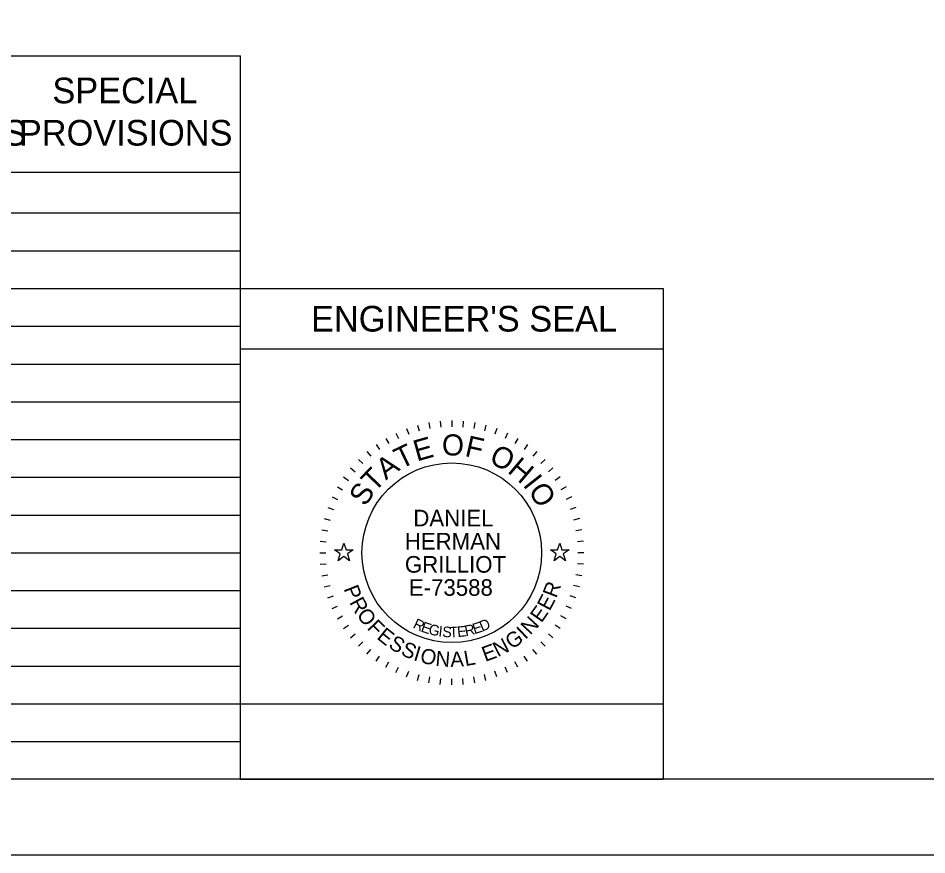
# Model space of a CAD drawing. Extents: x 0 to 34, y 0 to 22.
# Drawn here: x 22.13 to 28.15, y 0 to 5.54 of the extents above; entities that cross this region are included whole.
import ezdxf

# ---------------------------------------------------------------- set-up
doc = ezdxf.new("R2010")
doc.units = 0
for name, color, linetype in [('SH_Border', 7, 'Continuous'), ('SH_Cut_Line', 7, 'Continuous'), ('SH_Data', 7, 'Continuous'), ('SH_Seal', 7, 'Continuous'), ('SH_Text', 7, 'Continuous')]:
    doc.layers.add(name, color=color, linetype=linetype)

msp = doc.modelspace()

# ---------------------------------------------------------------- linework, layer by layer
at = {"layer": 'SH_Border'}
msp.add_lwpolyline([(1.5, 21.5), (33.5, 21.5), (33.5, 0.5), (1.5, 0.5)], close=True, dxfattribs=at)
at = {"layer": 'SH_Cut_Line'}
msp.add_lwpolyline([(0, 0), (34, 0), (34, 22), (0, 22)], close=True, dxfattribs=at)
at = {"layer": 'SH_Data'}
for p, q in [((10.15, 5.2917), (23.6, 5.2917)), ((23.6, 0.5), (23.6, 5.2917)), ((10.15, 4.5209), (23.6, 4.5209)), ((10.15, 4.25), (23.6, 4.25)), ((10.15, 4), (23.6, 4)), ((10.15, 3.75), (23.6, 3.75)), ((23.6, 0.5), (23.6, 3.75)), ((23.6, 3.75), (26.4, 3.75)), ((26.4, 3.75), (26.4, 0.5)), ((10.15, 3.5), (23.6, 3.5)), ((23.6, 3.35), (26.4, 3.35)), ((10.15, 3.25), (23.6, 3.25)), ((10.15, 3), (23.6, 3)), ((10.15, 2.75), (23.6, 2.75)), ((10.15, 2.5), (23.6, 2.5)), ((10.15, 2.25), (23.6, 2.25)), ((10.15, 2), (23.6, 2)), ((10.15, 1.75), (23.6, 1.75)), ((10.15, 1.5), (23.6, 1.5)), ((10.15, 1.25), (23.6, 1.25)), ((10.15, 1), (23.6, 1)), ((10.15, 0.75), (23.6, 0.75)), ((23.6, 0.5), (26.4, 0.5))]:
    msp.add_line(p, q, dxfattribs=at)
msp.add_lwpolyline([(23.6, 0.5), (23.6, 1), (26.4, 1), (26.4, 0.5)], close=True, dxfattribs=at)
at = {"layer": 'SH_Seal'}
for p, q in [((24.7735, 2.8452), (24.7839, 2.8065)), ((24.8481, 2.8617), (24.855, 2.8223)), ((24.9237, 2.8717), (24.9272, 2.8318)), ((25, 2.875), (25, 2.835)), ((25.0763, 2.8717), (25.0728, 2.8318)), ((25.1519, 2.8617), (25.145, 2.8223)), ((25.2265, 2.8452), (25.2161, 2.8065)), ((24.6302, 2.793), (24.6471, 2.7568)), ((24.7007, 2.8222), (24.7144, 2.7846)), ((25.2993, 2.8222), (25.2856, 2.7846)), ((25.3698, 2.793), (25.3529, 2.7568)), ((24.4981, 2.7168), (24.5211, 2.684)), ((24.5625, 2.7578), (24.5825, 2.7231)), ((25.4375, 2.7578), (25.4175, 2.7231)), ((25.5019, 2.7168), (25.4789, 2.684)), ((24.4376, 2.6703), (24.4633, 2.6396)), ((25.5624, 2.6703), (25.5367, 2.6396)), ((24.3813, 2.6187), (24.4096, 2.5904)), ((25.6187, 2.6187), (25.5904, 2.5904)), ((24.3297, 2.5624), (24.3604, 2.5367)), ((25.6703, 2.5624), (25.6396, 2.5367)), ((24.2832, 2.5019), (24.316, 2.4789)), ((25.7168, 2.5019), (25.684, 2.4789)), ((24.2422, 2.4375), (24.2769, 2.4175)), ((25.7578, 2.4375), (25.7231, 2.4175)), ((24.207, 2.3698), (24.2432, 2.3529)), ((25.793, 2.3698), (25.7568, 2.3529)), ((24.1778, 2.2993), (24.2154, 2.2856)), ((25.8222, 2.2993), (25.7846, 2.2856)), ((24.1548, 2.2265), (24.1935, 2.2161)), ((25.8452, 2.2265), (25.8065, 2.2161)), ((24.1383, 2.1519), (24.1777, 2.145)), ((25.8617, 2.1519), (25.8223, 2.145)), ((24.1283, 2.0763), (24.1682, 2.0728)), ((25.8717, 2.0763), (25.8318, 2.0728)), ((24.125, 2), (24.165, 2)), ((25.875, 2), (25.835, 2)), ((24.1283, 1.9237), (24.1682, 1.9272)), ((25.8717, 1.9237), (25.8318, 1.9272)), ((24.1383, 1.8481), (24.1777, 1.855)), ((25.8617, 1.8481), (25.8223, 1.855)), ((24.1548, 1.7735), (24.1935, 1.7839)), ((25.8452, 1.7735), (25.8065, 1.7839)), ((24.1778, 1.7007), (24.2154, 1.7144)), ((25.8222, 1.7007), (25.7846, 1.7144)), ((24.207, 1.6302), (24.2432, 1.6471)), ((25.793, 1.6302), (25.7568, 1.6471)), ((24.2422, 1.5625), (24.2769, 1.5825)), ((25.7578, 1.5625), (25.7231, 1.5825)), ((24.2832, 1.4981), (24.316, 1.5211)), ((25.7168, 1.4981), (25.684, 1.5211)), ((24.3297, 1.4376), (24.3604, 1.4633)), ((25.6703, 1.4376), (25.6396, 1.4633)), ((24.3813, 1.3813), (24.4096, 1.4096)), ((25.6187, 1.3813), (25.5904, 1.4096)), ((24.4376, 1.3297), (24.4633, 1.3604)), ((25.5624, 1.3297), (25.5367, 1.3604)), ((24.4981, 1.2832), (24.5211, 1.316)), ((24.5625, 1.2422), (24.5825, 1.2769)), ((25.4375, 1.2422), (25.4175, 1.2769)), ((25.5019, 1.2832), (25.4789, 1.316)), ((24.6302, 1.207), (24.6471, 1.2432)), ((24.7007, 1.1778), (24.7144, 1.2154)), ((25.2993, 1.1778), (25.2856, 1.2154)), ((25.3698, 1.207), (25.3529, 1.2432)), ((24.7735, 1.1548), (24.7839, 1.1935)), ((24.8481, 1.1383), (24.855, 1.1777)), ((24.9237, 1.1283), (24.9272, 1.1682)), ((25, 1.125), (25, 1.165)), ((25.0763, 1.1283), (25.0728, 1.1682)), ((25.1519, 1.1383), (25.145, 1.1777)), ((25.2265, 1.1548), (25.2161, 1.1935))]:
    msp.add_line(p, q, dxfattribs=at)
for points in [[(24.2236, 2.02), (24.2705, 2.02), (24.285, 2.0645), (24.2995, 2.02), (24.3464, 2.02), (24.3085, 1.9924), (24.323, 1.9478), (24.285, 1.9754), (24.247, 1.9478), (24.2615, 1.9924)], [(25.6536, 2.02), (25.7005, 2.02), (25.715, 2.0645), (25.7295, 2.02), (25.7764, 2.02), (25.7385, 1.9924), (25.753, 1.9478), (25.715, 1.9754), (25.677, 1.9478), (25.6915, 1.9924)]]:
    msp.add_lwpolyline(points, close=True, dxfattribs=at)
msp.add_circle((25, 2), 0.595, dxfattribs=at)

# ---------------------------------------------------------------- texts
at = {"layer": 'SH_Data'}
msp.add_text("ENGINEER'S SEAL", height=0.17, dxfattribs=at).set_placement((24.0676, 3.465))
at = {"layer": 'SH_Seal'}
for s, height, rotation, p in [('E', 0.14, 15.75706, (24.7684, 2.6038)), ('O', 0.14, 359.78119, (24.9347, 2.6443)), ('F', 0.14, 347.43619, (25.0811, 2.6417)), ('T', 0.14, 25.71674, (24.6616, 2.5518)), ('O', 0.14, 332.25863, (25.2398, 2.6015)), ('A', 0.14, 36.47472, (24.5634, 2.4781)), ('H', 0.14, 319.91363, (25.3632, 2.5361)), ('T', 0.14, 46.4344, (24.4883, 2.3964)), ('I', 0.14, 308.36695, (25.4665, 2.4483)), ('S', 0.14, 57.19238, (24.4281, 2.3014)), ('O', 0.14, 303.14906, (25.5021, 2.4089)), ('R', 0.1, 69.23216, (25.6919, 1.6954)), ('P', 0.1, 291.49398, (24.2823, 1.7621)), ('R', 0.1, 298.73106, (24.319, 1.6717)), ('E', 0.1, 61.99508, (25.6476, 1.6098)), ('O', 0.1, 306.46664, (24.3655, 1.5883)), ('E', 0.1, 54.75801, (25.5933, 1.5314)), ('N', 0.1, 47.02243, (25.5202, 1.4508)), ('F', 0.1, 314.7068, (24.4343, 1.4983)), ('E', 0.1, 321.43929, (24.4978, 1.4348)), ('R', 0.07, 334.48695, (24.7375, 1.5051)), ('E', 0.07, 341.03996, (24.7906, 1.4801)), ('G', 0.07, 347.47515, (24.8414, 1.4618)), ('I', 0.07, 353.78581, (24.9091, 1.4468)), ('S', 0.07, 356.89262, (24.9358, 1.4429)), ('T', 0.07, 3.00609, (24.9857, 1.4387)), ('E', 0.07, 6.01169, (25.0389, 1.4412)), ('R', 0.07, 11.91844, (25.0925, 1.4474)), ('E', 0.07, 17.68363, (25.1498, 1.4602)), ('D', 0.07, 23.30524, (25.201, 1.477)), ('I', 0.1, 43.28703, (25.4868, 1.4214)), ('S', 0.1, 328.67637, (24.5743, 1.3752)), ('G', 0.1, 35.04687, (25.3981, 1.357)), ('S', 0.1, 335.91345, (24.6564, 1.3266)), ('E', 0.1, 20.07421, (25.2212, 1.277)), ('N', 0.1, 27.31129, (25.3045, 1.3075)), ('I', 0.1, 343.15053, (24.7406, 1.2897)), ('O', 0.1, 346.88592, (24.7839, 1.2751)), ('N', 0.1, 355.12608, (24.8888, 1.2517)), ('A', 0.1, 2.86166, (24.9923, 1.2437)), ('L', 0.1, 10.09874, (25.0894, 1.249))]:
    msp.add_text(s, height=height, rotation=rotation, dxfattribs=at).set_placement(p)
for s, p in [('DANIEL', (24.7451, 2.1749)), ('HERMAN', (24.6885, 2.0216)), ('GRILLIOT', (24.6892, 1.8684)), ('E-73588', (24.7157, 1.7151))]:
    msp.add_text(s, height=0.11, dxfattribs=at).set_placement(p)
at = {"layer": 'SH_Text'}
for s, p in [('SPECIAL', (22.3542, 4.9763)), ('SPECIFICATIONS', (20.2871, 4.6963)), ('PROVISIONS', (22.1323, 4.6963))]:
    msp.add_text(s, height=0.17, dxfattribs=at).set_placement(p)

doc.saveas('drawing.dxf')
